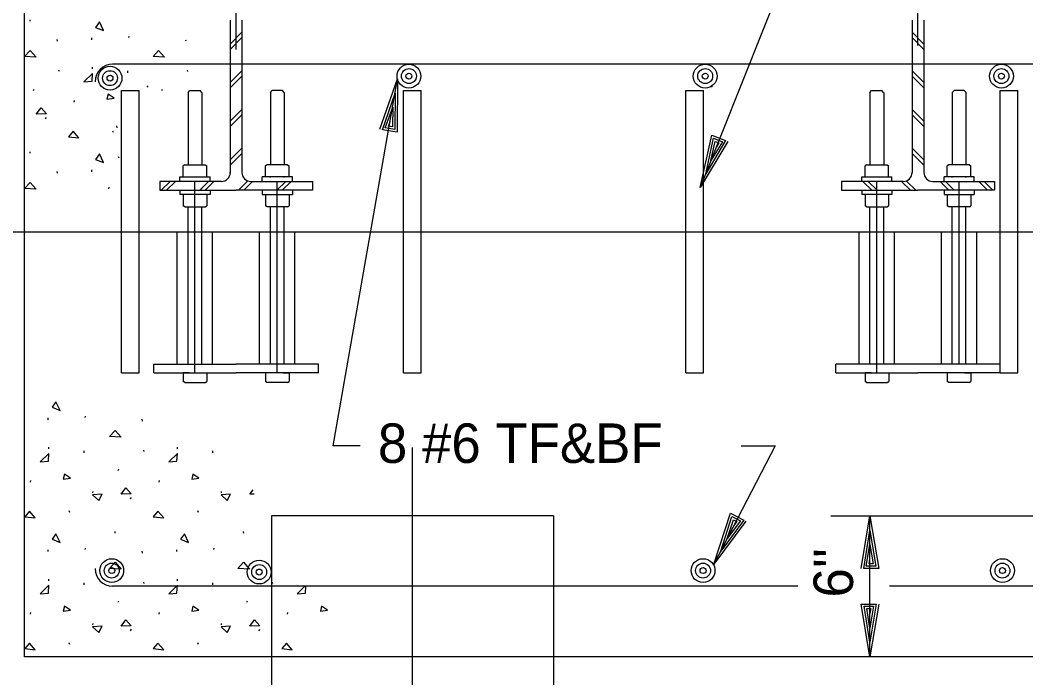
# Model space of a CAD drawing. Extents: x 0 to 320, y -4 to 473.
# Drawn here: x 9.87 to 13.435, y 14.093 to 16.424 of the extents above; entities that cross this region are included whole.
import ezdxf

# ---------------------------------------------------------------- set-up
doc = ezdxf.new("R2010")
doc.units = 0
for name, color, linetype in [('Level 10', 7, 'Continuous'), ('Level 2', 7, 'Continuous'), ('Level 3', 7, 'Continuous'), ('Level 44', 7, 'Continuous'), ('Level 50', 7, 'Continuous')]:
    doc.layers.add(name, color=color, linetype=linetype)

msp = doc.modelspace()

# ---------------------------------------------------------------- linework, layer by layer
at = {"layer": 'Level 10'}
for p, q in [((9.9062, 16.4199), (9.9058, 16.425)), ((10.2558, 16.3615), (10.2566, 16.3662)), ((10.0032, 16.3491), (10.0014, 16.3553)), ((10.1244, 16.3541), (10.1244, 16.3603)), ((10.4587, 16.3491), (10.4579, 16.352)), ((10.1266, 16.2504), (10.1266, 16.2563)), ((10.0094, 16.2413), (10.0077, 16.2458)), ((10.2519, 16.237), (10.2519, 16.2433)), ((10.4649, 16.2413), (10.4632, 16.2458)), ((10.3239, 16.1857), (10.3211, 16.1912)), ((12.3239, 16.1857), (12.3211, 16.1912)), ((9.9173, 16.1745), (9.9196, 16.1794)), ((10.3729, 16.1745), (10.3752, 16.1794)), ((10.0619, 16.1325), (10.0629, 16.1386)), ((9.9604, 16.0737), (9.9635, 16.0789)), ((10.2148, 16.0423), (10.213, 16.0485)), ((10.2013, 16.0249), (10.1985, 16.0304)), ((9.9062, 15.9523), (9.9058, 15.9574)), ((10.221, 15.9345), (10.2192, 15.9389)), ((10.0032, 15.8815), (10.0014, 15.8877)), ((10.1244, 15.8865), (10.1244, 15.8927)), ((10.1845, 15.8257), (10.1855, 15.8318)), ((9.97, 15.0077), (9.97, 15.014)), ((10.1013, 15.0151), (10.1022, 15.0198)), ((10.3043, 15.0027), (10.3025, 15.009)), ((9.9722, 14.9041), (9.9722, 14.9099)), ((10.4277, 14.9041), (10.4277, 14.9099)), ((10.0975, 14.8906), (10.0975, 14.8969)), ((10.3105, 14.8949), (10.3087, 14.8994)), ((10.553, 14.8906), (10.553, 14.8969)), ((10.2184, 14.8281), (10.2207, 14.833)), ((9.9075, 14.7861), (9.9084, 14.7922)), ((10.363, 14.7861), (10.3639, 14.7922)), ((10.1284, 14.7481), (10.1288, 14.7527)), ((10.2614, 14.7273), (10.2646, 14.7325)), ((10.5839, 14.7481), (10.5844, 14.7527)), ((10.0469, 14.6785), (10.0441, 14.6841)), ((10.5024, 14.6785), (10.4996, 14.6841)), ((10.2073, 14.6059), (10.2069, 14.611)), ((10.6628, 14.6059), (10.6624, 14.611)), ((9.97, 14.5401), (9.97, 14.5464)), ((10.1013, 14.5475), (10.1022, 14.5522)), ((10.4255, 14.5401), (10.4255, 14.5464)), ((10.5569, 14.5475), (10.5577, 14.5522)), ((10.3043, 14.5351), (10.3025, 14.5414)), ((9.9722, 14.4365), (9.9722, 14.4423)), ((10.4277, 14.4365), (10.4277, 14.4423)), ((10.0975, 14.423), (10.0975, 14.4293)), ((10.3105, 14.4273), (10.3087, 14.4318)), ((10.553, 14.423), (10.553, 14.4293)), ((10.766, 14.4273), (10.7643, 14.4318)), ((10.2184, 14.3605), (10.2207, 14.3654)), ((10.6739, 14.3605), (10.6762, 14.3654)), ((9.9075, 14.3185), (9.9084, 14.3246)), ((10.363, 14.3185), (10.3639, 14.3246)), ((10.8185, 14.3185), (10.8195, 14.3246)), ((10.1284, 14.2805), (10.1288, 14.2851)), ((10.2614, 14.2597), (10.2646, 14.2649)), ((10.5839, 14.2805), (10.5844, 14.2851)), ((10.717, 14.2597), (10.7201, 14.2649)), ((10.0469, 14.2109), (10.0441, 14.2165)), ((10.5024, 14.2109), (10.4996, 14.2165))]:
    msp.add_line(p, q, dxfattribs=at)
for points in [[(10.138, 16.3978), (10.1664, 16.3868), (10.1514, 16.4175)], [(9.8858, 16.2948), (9.9056, 16.3163), (9.9268, 16.2925)], [(10.3413, 16.2948), (10.3611, 16.3163), (10.3823, 16.2925)], [(10.1251, 16.207), (10.1266, 16.2348), (10.0958, 16.2047)], [(10.1779, 16.1435), (10.2032, 16.1467), (10.1819, 16.161)], [(9.9277, 16.0901), (9.9444, 16.1123), (9.9633, 16.091)], [(10.0785, 16.0062), (10.0579, 16.0299), (10.0413, 16.0102)], [(10.138, 15.9302), (10.1664, 15.9192), (10.1514, 15.9499)], [(9.8858, 15.8272), (9.9056, 15.8487), (9.9268, 15.8249)], [(9.9835, 15.0515), (10.012, 15.0404), (9.997, 15.0711)], [(10.1869, 14.9484), (10.2067, 14.9699), (10.2279, 14.9461)], [(9.9706, 14.8606), (9.9722, 14.8884), (9.9413, 14.8583)], [(10.4261, 14.8606), (10.4277, 14.8884), (10.3969, 14.8583)], [(10.0234, 14.7971), (10.0487, 14.8003), (10.0275, 14.8146)], [(10.4789, 14.7971), (10.5043, 14.8003), (10.483, 14.8146)], [(10.2287, 14.7438), (10.2455, 14.7659), (10.2644, 14.7446)], [(10.1269, 14.7414), (10.1491, 14.7216), (10.1609, 14.7438)], [(10.5824, 14.7414), (10.6046, 14.7216), (10.6164, 14.7438)], [(9.9241, 14.6598), (9.9034, 14.6835), (9.8869, 14.6639)], [(10.3796, 14.6598), (10.3589, 14.6835), (10.3424, 14.6639)], [(9.9835, 14.5839), (10.012, 14.5728), (9.997, 14.6035)], [(10.4391, 14.5839), (10.4675, 14.5728), (10.4525, 14.6035)], [(10.1869, 14.4808), (10.2067, 14.5023), (10.2279, 14.4785)], [(10.6424, 14.4808), (10.6622, 14.5023), (10.6834, 14.4785)], [(9.9706, 14.393), (9.9722, 14.4208), (9.9413, 14.3907)], [(10.4261, 14.393), (10.4277, 14.4208), (10.3969, 14.3907)], [(10.0234, 14.3295), (10.0487, 14.3327), (10.0275, 14.347)], [(10.4789, 14.3295), (10.5043, 14.3327), (10.483, 14.347)], [(10.9345, 14.3295), (10.9598, 14.3327), (10.9385, 14.347)], [(10.2287, 14.2761), (10.2455, 14.2983), (10.2644, 14.277)], [(10.6843, 14.2761), (10.701, 14.2983), (10.7199, 14.277)], [(10.1269, 14.2738), (10.1491, 14.254), (10.1609, 14.2761)], [(10.5824, 14.2738), (10.6046, 14.254), (10.6164, 14.2761)], [(9.9241, 14.1922), (9.9034, 14.2159), (9.8869, 14.1963)], [(10.3796, 14.1922), (10.3589, 14.2159), (10.3424, 14.1963)], [(10.8351, 14.1922), (10.8145, 14.2159), (10.7979, 14.1963)]]:
    msp.add_lwpolyline(points, close=True, dxfattribs=at)
for points in [[(10.6843, 14.7438), (10.6961, 14.7594)], [(10.7004, 14.7441), (10.6843, 14.7438)], [(10.8807, 14.4184), (10.8524, 14.3907), (10.8817, 14.393)], [(10.8817, 14.393), (10.883, 14.4165)]]:
    msp.add_lwpolyline(points, dxfattribs=at)
at = {"layer": 'Level 2'}
for p, q in [((9.8858, 14.1673), (9.8858, 16.5173)), ((10.615, 16.4236), (10.615, 15.8809)), ((10.6567, 16.4236), (10.6567, 15.8809)), ((13.0317, 16.4236), (13.0317, 15.8809)), ((13.0733, 16.4236), (13.0733, 15.8809)), ((10.615, 16.3388), (10.6567, 16.3804)), ((10.615, 16.3199), (10.6567, 16.3616)), ((13.0733, 16.3388), (13.0317, 16.3804)), ((13.0733, 16.3199), (13.0317, 16.3616)), ((15.4483, 16.2673), (10.1983, 16.2673)), ((10.615, 16.2021), (10.6567, 16.2437)), ((10.615, 16.1832), (10.6567, 16.2249)), ((13.0733, 16.2021), (13.0317, 16.2437)), ((13.0733, 16.1832), (13.0317, 16.2249)), ((10.2296, 15.1736), (10.2296, 16.1736)), ((10.2921, 15.1736), (10.2921, 16.1736)), ((10.4656, 16.1675), (10.4717, 16.1736)), ((10.4658, 16.1675), (10.4658, 15.9107)), ((10.4717, 16.1736), (10.5081, 16.1736)), ((10.5141, 16.1675), (10.5081, 16.1736)), ((10.5143, 16.1675), (10.5143, 15.9107)), ((10.7574, 16.1675), (10.7574, 15.9107)), ((10.7575, 16.1675), (10.7636, 16.1736)), ((10.8, 16.1736), (10.7636, 16.1736)), ((10.806, 16.1675), (10.8, 16.1736)), ((10.8059, 16.1675), (10.8059, 15.9107)), ((11.2296, 15.1736), (11.2296, 16.1736)), ((11.2921, 15.1736), (11.2921, 16.1736)), ((12.2296, 15.1736), (12.2296, 16.1736)), ((12.2921, 15.1736), (12.2921, 16.1736)), ((12.8823, 16.1675), (12.8883, 16.1736)), ((12.8824, 16.1675), (12.8824, 15.9107)), ((12.8883, 16.1736), (12.9247, 16.1736)), ((12.9308, 16.1675), (12.9247, 16.1736)), ((12.9309, 16.1675), (12.9309, 15.9107)), ((13.1741, 16.1675), (13.1741, 15.9107)), ((13.1742, 16.1675), (13.1803, 16.1736)), ((13.2166, 16.1736), (13.1803, 16.1736)), ((13.2227, 16.1675), (13.2166, 16.1736)), ((13.2226, 16.1675), (13.2226, 15.9107)), ((13.3442, 15.1736), (13.3442, 16.1736)), ((13.4067, 15.1736), (13.4067, 16.1736)), ((10.615, 16.0654), (10.6567, 16.107)), ((10.615, 16.0465), (10.6567, 16.0882)), ((13.0733, 16.0654), (13.0317, 16.107)), ((13.0733, 16.0465), (13.0317, 16.0882)), ((10.615, 15.9286), (10.6567, 15.9703)), ((13.0733, 15.9286), (13.0317, 15.9703)), ((10.615, 15.9098), (10.6567, 15.9515)), ((13.0733, 15.9098), (13.0317, 15.9515)), ((10.4537, 15.9107), (10.4481, 15.9075)), ((10.4481, 15.8677), (10.4481, 15.9075)), ((10.4537, 15.9107), (10.5263, 15.9107)), ((10.5263, 15.9107), (10.5319, 15.9075)), ((10.5319, 15.8677), (10.5319, 15.9075)), ((10.7454, 15.9107), (10.7398, 15.9075)), ((10.7398, 15.8677), (10.7398, 15.9075)), ((10.8179, 15.9107), (10.7454, 15.9107)), ((10.8179, 15.9107), (10.8235, 15.9075)), ((10.8235, 15.8677), (10.8235, 15.9075)), ((12.8704, 15.9107), (12.8648, 15.9075)), ((12.8648, 15.8677), (12.8648, 15.9075)), ((12.8704, 15.9107), (12.9429, 15.9107)), ((12.9429, 15.9107), (12.9485, 15.9075)), ((12.9485, 15.8677), (12.9485, 15.9075)), ((13.1621, 15.9107), (13.1565, 15.9075)), ((13.1565, 15.8677), (13.1565, 15.9075)), ((13.2346, 15.9107), (13.1621, 15.9107)), ((13.2346, 15.9107), (13.2402, 15.9075)), ((13.2402, 15.8677), (13.2402, 15.9075)), ((10.4365, 15.8677), (10.5435, 15.8677)), ((10.4365, 15.8521), (10.4365, 15.8677)), ((10.4658, 15.8662), (10.4658, 15.8677)), ((10.5143, 15.8662), (10.5143, 15.8677)), ((10.5435, 15.8521), (10.5435, 15.8677)), ((10.8352, 15.8677), (10.7281, 15.8677)), ((10.7281, 15.8521), (10.7281, 15.8677)), ((10.7574, 15.8662), (10.7574, 15.8677)), ((10.8059, 15.8662), (10.8059, 15.8677)), ((10.8352, 15.8521), (10.8352, 15.8677)), ((12.8531, 15.8677), (12.9602, 15.8677)), ((12.8531, 15.8521), (12.8531, 15.8677)), ((12.8824, 15.8662), (12.8824, 15.8677)), ((12.9309, 15.8662), (12.9309, 15.8677)), ((12.9602, 15.8521), (12.9602, 15.8677)), ((13.2519, 15.8677), (13.1448, 15.8677)), ((13.1448, 15.8521), (13.1448, 15.8677)), ((13.1741, 15.8662), (13.1741, 15.8677)), ((13.2226, 15.8662), (13.2226, 15.8677)), ((13.2519, 15.8521), (13.2519, 15.8677)), ((10.5837, 15.8521), (10.365, 15.8521)), ((10.365, 15.8521), (10.365, 15.8209)), ((10.3705, 15.8209), (10.4018, 15.8521)), ((10.3894, 15.8209), (10.4206, 15.8521)), ((10.49, 15.1736), (10.49, 15.8496)), ((10.5072, 15.8209), (10.5385, 15.8521)), ((10.5261, 15.8209), (10.5573, 15.8521)), ((10.6439, 15.8209), (10.6771, 15.8541)), ((10.6628, 15.8209), (10.694, 15.8521)), ((10.6879, 15.8521), (10.9067, 15.8521)), ((10.7806, 15.8209), (10.8119, 15.8521)), ((10.7817, 15.1736), (10.7817, 15.8496)), ((10.7995, 15.8209), (10.8307, 15.8521)), ((10.9067, 15.8521), (10.9067, 15.8209)), ((13.0004, 15.8521), (12.7817, 15.8521)), ((12.7817, 15.8521), (12.7817, 15.8209)), ((12.8888, 15.8209), (12.8576, 15.8521)), ((12.9077, 15.8209), (12.8764, 15.8521)), ((12.9067, 15.1736), (12.9067, 15.8496)), ((13.0255, 15.8209), (12.9943, 15.8521)), ((13.0444, 15.8209), (13.0112, 15.8541)), ((13.1046, 15.8521), (13.3233, 15.8521)), ((13.1622, 15.8209), (13.131, 15.8521)), ((13.1811, 15.8209), (13.1498, 15.8521)), ((13.1983, 15.2048), (13.1983, 15.8496)), ((13.2989, 15.8209), (13.2677, 15.8521)), ((13.3178, 15.8209), (13.2866, 15.8521)), ((13.3233, 15.8521), (13.3233, 15.8209)), ((10.365, 15.8209), (10.6358, 15.8209)), ((10.4365, 15.8209), (10.4365, 15.8053)), ((10.5435, 15.8053), (10.4365, 15.8053)), ((10.4481, 15.8053), (10.4481, 15.7655)), ((10.4658, 15.8068), (10.4658, 15.8053)), ((10.5143, 15.8068), (10.5143, 15.8053)), ((10.5319, 15.8053), (10.5319, 15.7655)), ((10.5435, 15.8209), (10.5435, 15.8053)), ((10.9067, 15.8209), (10.6358, 15.8209)), ((10.7281, 15.8209), (10.7281, 15.8053)), ((10.7281, 15.8053), (10.8352, 15.8053)), ((10.7398, 15.8053), (10.7398, 15.7655)), ((10.7574, 15.8068), (10.7574, 15.8053)), ((10.8059, 15.8068), (10.8059, 15.8053)), ((10.8235, 15.8053), (10.8235, 15.7655)), ((10.8352, 15.8209), (10.8352, 15.8053)), ((12.7817, 15.8209), (13.0525, 15.8209)), ((12.8531, 15.8209), (12.8531, 15.8053)), ((12.9602, 15.8053), (12.8531, 15.8053)), ((12.8648, 15.8053), (12.8648, 15.7655)), ((12.8824, 15.8068), (12.8824, 15.8053)), ((12.9309, 15.8068), (12.9309, 15.8053)), ((12.9485, 15.8053), (12.9485, 15.7655)), ((12.9602, 15.8209), (12.9602, 15.8053)), ((13.3233, 15.8209), (13.0525, 15.8209)), ((13.1448, 15.8209), (13.1448, 15.8053)), ((13.1448, 15.8053), (13.2519, 15.8053)), ((13.1565, 15.8053), (13.1565, 15.7655)), ((13.1741, 15.8068), (13.1741, 15.8053)), ((13.2226, 15.8068), (13.2226, 15.8053)), ((13.2402, 15.8053), (13.2402, 15.7655)), ((13.2519, 15.8209), (13.2519, 15.8053)), ((10.4537, 15.7623), (10.4481, 15.7655)), ((10.4537, 15.7623), (10.5263, 15.7623)), ((10.4658, 15.2048), (10.4658, 15.7623)), ((10.5143, 15.2048), (10.5143, 15.7623)), ((10.5263, 15.7623), (10.5319, 15.7655)), ((10.7454, 15.7623), (10.7398, 15.7655)), ((10.8179, 15.7623), (10.7454, 15.7623)), ((10.7574, 15.2048), (10.7574, 15.7623)), ((10.8059, 15.2048), (10.8059, 15.7623)), ((10.8179, 15.7623), (10.8235, 15.7655)), ((12.8704, 15.7623), (12.8648, 15.7655)), ((12.8704, 15.7623), (12.9429, 15.7623)), ((12.8824, 15.2048), (12.8824, 15.7623)), ((12.9309, 15.2048), (12.9309, 15.7623)), ((12.9429, 15.7623), (12.9485, 15.7655)), ((13.1621, 15.7623), (13.1565, 15.7655)), ((13.2346, 15.7623), (13.1621, 15.7623)), ((13.1741, 15.2048), (13.1741, 15.7623)), ((13.2226, 15.2048), (13.2226, 15.7623)), ((13.2346, 15.7623), (13.2402, 15.7655)), ((9.5414, 15.6736), (15.7608, 15.6736)), ((10.4275, 15.2048), (10.4275, 15.6736)), ((10.5525, 15.2048), (10.5525, 15.6736)), ((10.7192, 15.2048), (10.7192, 15.6736)), ((10.8442, 15.2048), (10.8442, 15.6736)), ((12.8442, 15.2048), (12.8442, 15.6736)), ((12.9692, 15.2048), (12.9692, 15.6736)), ((13.1358, 15.2048), (13.1358, 15.6736)), ((13.2608, 15.2048), (13.2608, 15.6736)), ((10.3442, 15.2048), (10.6358, 15.2048)), ((10.3442, 15.1736), (10.3442, 15.2048)), ((10.9275, 15.2048), (10.6358, 15.2048)), ((10.9275, 15.1736), (10.9275, 15.2048)), ((12.7608, 15.1736), (12.7608, 15.2048)), ((13.0525, 15.2048), (12.7608, 15.2048)), ((13.3442, 15.2048), (13.0525, 15.2048)), ((13.3442, 15.1736), (13.3442, 15.2048)), ((10.3442, 15.1736), (10.6358, 15.1736)), ((10.4695, 15.1734), (10.4484, 15.1734)), ((10.4484, 15.1734), (10.4484, 15.1428)), ((10.466, 15.175), (10.466, 15.1734)), ((10.5145, 15.175), (10.5145, 15.1734)), ((10.5321, 15.1734), (10.5321, 15.1428)), ((10.9275, 15.1736), (10.6358, 15.1736)), ((10.7395, 15.1734), (10.7395, 15.1428)), ((10.7572, 15.175), (10.7572, 15.1734)), ((10.8021, 15.1734), (10.8233, 15.1734)), ((10.8057, 15.175), (10.8057, 15.1734)), ((10.8233, 15.1734), (10.8233, 15.1428)), ((12.7608, 15.1736), (13.0525, 15.1736)), ((12.8862, 15.1734), (12.865, 15.1734)), ((12.865, 15.1734), (12.865, 15.1428)), ((12.8826, 15.175), (12.8826, 15.1734)), ((12.9311, 15.175), (12.9311, 15.1734)), ((12.9488, 15.1734), (12.9488, 15.1428)), ((13.3442, 15.1736), (13.0525, 15.1736)), ((13.1562, 15.1734), (13.1562, 15.1428)), ((13.1738, 15.175), (13.1738, 15.1734)), ((13.2188, 15.1734), (13.24, 15.1734)), ((13.2223, 15.175), (13.2223, 15.1734)), ((13.24, 15.1734), (13.24, 15.1428)), ((10.454, 15.1395), (10.4484, 15.1428)), ((10.454, 15.1395), (10.5265, 15.1395)), ((10.5265, 15.1395), (10.5321, 15.1428)), ((10.7452, 15.1395), (10.7395, 15.1428)), ((10.8177, 15.1395), (10.7452, 15.1395)), ((10.8177, 15.1395), (10.8233, 15.1428)), ((12.8706, 15.1395), (12.865, 15.1428)), ((12.8706, 15.1395), (12.9431, 15.1395)), ((12.9431, 15.1395), (12.9488, 15.1428)), ((13.1618, 15.1395), (13.1562, 15.1428)), ((13.2343, 15.1395), (13.1618, 15.1395)), ((13.2343, 15.1395), (13.24, 15.1428)), ((11.2608, 12.4674), (11.2608, 14.9095)), ((10.7608, 14.6673), (10.7608, 13.834)), ((11.7608, 14.6673), (10.7608, 14.6673)), ((11.7608, 14.6673), (11.7608, 13.834)), ((12.6265, 14.4173), (10.1983, 14.4173)), ((15.4483, 14.4173), (12.9518, 14.4173)), ((15.7608, 14.1673), (9.8858, 14.1673))]:
    msp.add_line(p, q, dxfattribs=at)
for centre, start, end in [((10.5837, 15.8834), 270, 360), ((10.6879, 15.8834), 180, 270), ((13.0004, 15.8834), 270, 360), ((13.1046, 15.8834), 180, 270)]:
    msp.add_arc(centre, 0.0313, start, end, dxfattribs=at)
at = {"layer": 'Level 3'}
for p, q in [((10.6358, 16.3189), (10.6358, 19.1678)), ((13.0525, 16.3341), (13.0525, 19.177)), ((10.1983, 16.2673), (10.1983, 16.2673)), ((11.2483, 16.2673), (11.2483, 16.2673)), ((12.2983, 16.2673), (12.2983, 16.2673)), ((13.3483, 16.2673), (13.3483, 16.2673)), ((11.2084, 16.2157), (11.2084, 16.2157)), ((11.1994, 16.1645), (11.1994, 16.1645)), ((12.3003, 15.8793), (12.3003, 15.8793)), ((12.281, 15.831), (12.281, 15.831)), ((12.7438, 14.6673), (13.6237, 14.6673)), ((12.8824, 14.1673), (12.8824, 14.6673)), ((12.3532, 14.5421), (12.3532, 14.5421)), ((12.3292, 14.4959), (12.3292, 14.4959))]:
    msp.add_line(p, q, dxfattribs=at)
for points in [[(12.1967, 16.9511), (12.7269, 16.9511), (12.281, 15.831)], [(11.0758, 14.9145), (10.9794, 14.9145), (11.2084, 16.2157)], [(11.1455, 16.0369), (11.2084, 16.2157), (11.2065, 16.0262), (11.1543, 16.0353), (11.1994, 16.1645), (11.1981, 16.0358), (11.1646, 16.0417), (11.1907, 16.1152), (11.1896, 16.0454), (11.1758, 16.0478), (11.1817, 16.064)], [(12.379, 15.9933), (12.281, 15.831), (12.3214, 16.0162), (12.3706, 15.9966), (12.3003, 15.8793), (12.3277, 16.0051), (12.3593, 15.9925), (12.3188, 15.9258), (12.3341, 15.9939), (12.3471, 15.9888), (12.338, 15.9741)], [(12.4256, 14.9145), (12.5462, 14.9145), (12.3292, 14.4959)], [(12.4428, 14.6477), (12.3292, 14.4959), (12.3877, 14.6762), (12.4348, 14.6518), (12.3532, 14.5421), (12.3929, 14.6645), (12.4231, 14.6488), (12.3762, 14.5864), (12.3981, 14.6528), (12.4106, 14.6463), (12.4001, 14.6326)]]:
    msp.add_lwpolyline(points, dxfattribs=at)
for centre, start, end in [((10.1983, 16.2048), 90, 180), ((10.1983, 14.4798), 180, 270)]:
    msp.add_arc(centre, 0.0625, start, end, dxfattribs=at)
at = {"layer": 'Level 44'}
for p, q in [((10.2296, 16.1736), (10.2921, 16.1736)), ((11.2296, 16.1736), (11.2921, 16.1736)), ((12.2296, 16.1736), (12.2921, 16.1736)), ((13.3442, 16.1736), (13.4067, 16.1736)), ((10.2296, 15.1736), (10.2921, 15.1736)), ((11.2296, 15.1736), (11.2921, 15.1736)), ((12.2296, 15.1736), (12.2921, 15.1736)), ((13.3442, 15.1736), (13.4067, 15.1736))]:
    msp.add_line(p, q, dxfattribs=at)
at = {"layer": 'Level 50'}
for p, q in [((12.8824, 14.6673), (12.8824, 14.6673)), ((12.8824, 14.6153), (12.8824, 14.6153)), ((12.8824, 14.2193), (12.8824, 14.2193)), ((12.8824, 14.1673), (12.8824, 14.1673))]:
    msp.add_line(p, q, dxfattribs=at)
for points in [[(12.8514, 14.4803), (12.8824, 14.6673), (12.9134, 14.4803), (12.8604, 14.4803), (12.8824, 14.6153), (12.9034, 14.4883), (12.8694, 14.4883), (12.8824, 14.5653), (12.8934, 14.4963), (12.8794, 14.4963), (12.8824, 14.5133)], [(12.9134, 14.3543), (12.8824, 14.1673), (12.8514, 14.3543), (12.9044, 14.3543), (12.8824, 14.2193), (12.8614, 14.3463), (12.8954, 14.3463), (12.8824, 14.2693), (12.8714, 14.3383), (12.8854, 14.3383), (12.8824, 14.3213)]]:
    msp.add_lwpolyline(points, dxfattribs=at)
for centre, radius in [((10.1889, 16.2179), 0.0422), ((11.2483, 16.2252), 0.0422), ((12.2983, 16.2252), 0.0422), ((13.3483, 16.2252), 0.0422), ((10.1889, 16.2179), 0.0264), ((10.1889, 16.2179), 0.0105), ((11.2483, 16.2252), 0.0264), ((11.2483, 16.2252), 0.0105), ((12.2983, 16.2252), 0.0264), ((12.2983, 16.2252), 0.0105), ((13.3483, 16.2252), 0.0264), ((13.3483, 16.2252), 0.0105), ((10.1951, 14.4729), 0.0422), ((10.7176, 14.4677), 0.0422), ((12.2907, 14.4729), 0.0422), ((13.3519, 14.4729), 0.0422), ((10.1951, 14.4729), 0.0264), ((10.1951, 14.4729), 0.0105), ((10.7176, 14.4677), 0.0264), ((10.7176, 14.4677), 0.0105), ((12.2907, 14.4729), 0.0264), ((12.2907, 14.4729), 0.0105), ((13.3519, 14.4729), 0.0264), ((13.3519, 14.4729), 0.0105)]:
    msp.add_circle(centre, radius, dxfattribs=at)

# ---------------------------------------------------------------- texts
at = {"layer": 'Level 3'}
msp.add_text('8 #6 TF&BF', height=0.14, dxfattribs=at).set_placement((11.1384, 14.8544))
msp.add_text("6''", height=0.14, rotation=90, dxfattribs=at).set_placement((12.8223, 14.3774))

doc.saveas('drawing.dxf')
